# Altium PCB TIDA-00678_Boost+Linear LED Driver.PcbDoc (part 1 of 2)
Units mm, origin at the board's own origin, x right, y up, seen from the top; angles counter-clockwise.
Board outline 111.76 x 61.72 mm, 2 copper layers (Top Layer, Bottom Layer), stack 1.575 mm thick; 183 components, 81 nets, 485 pads, 326 vias.
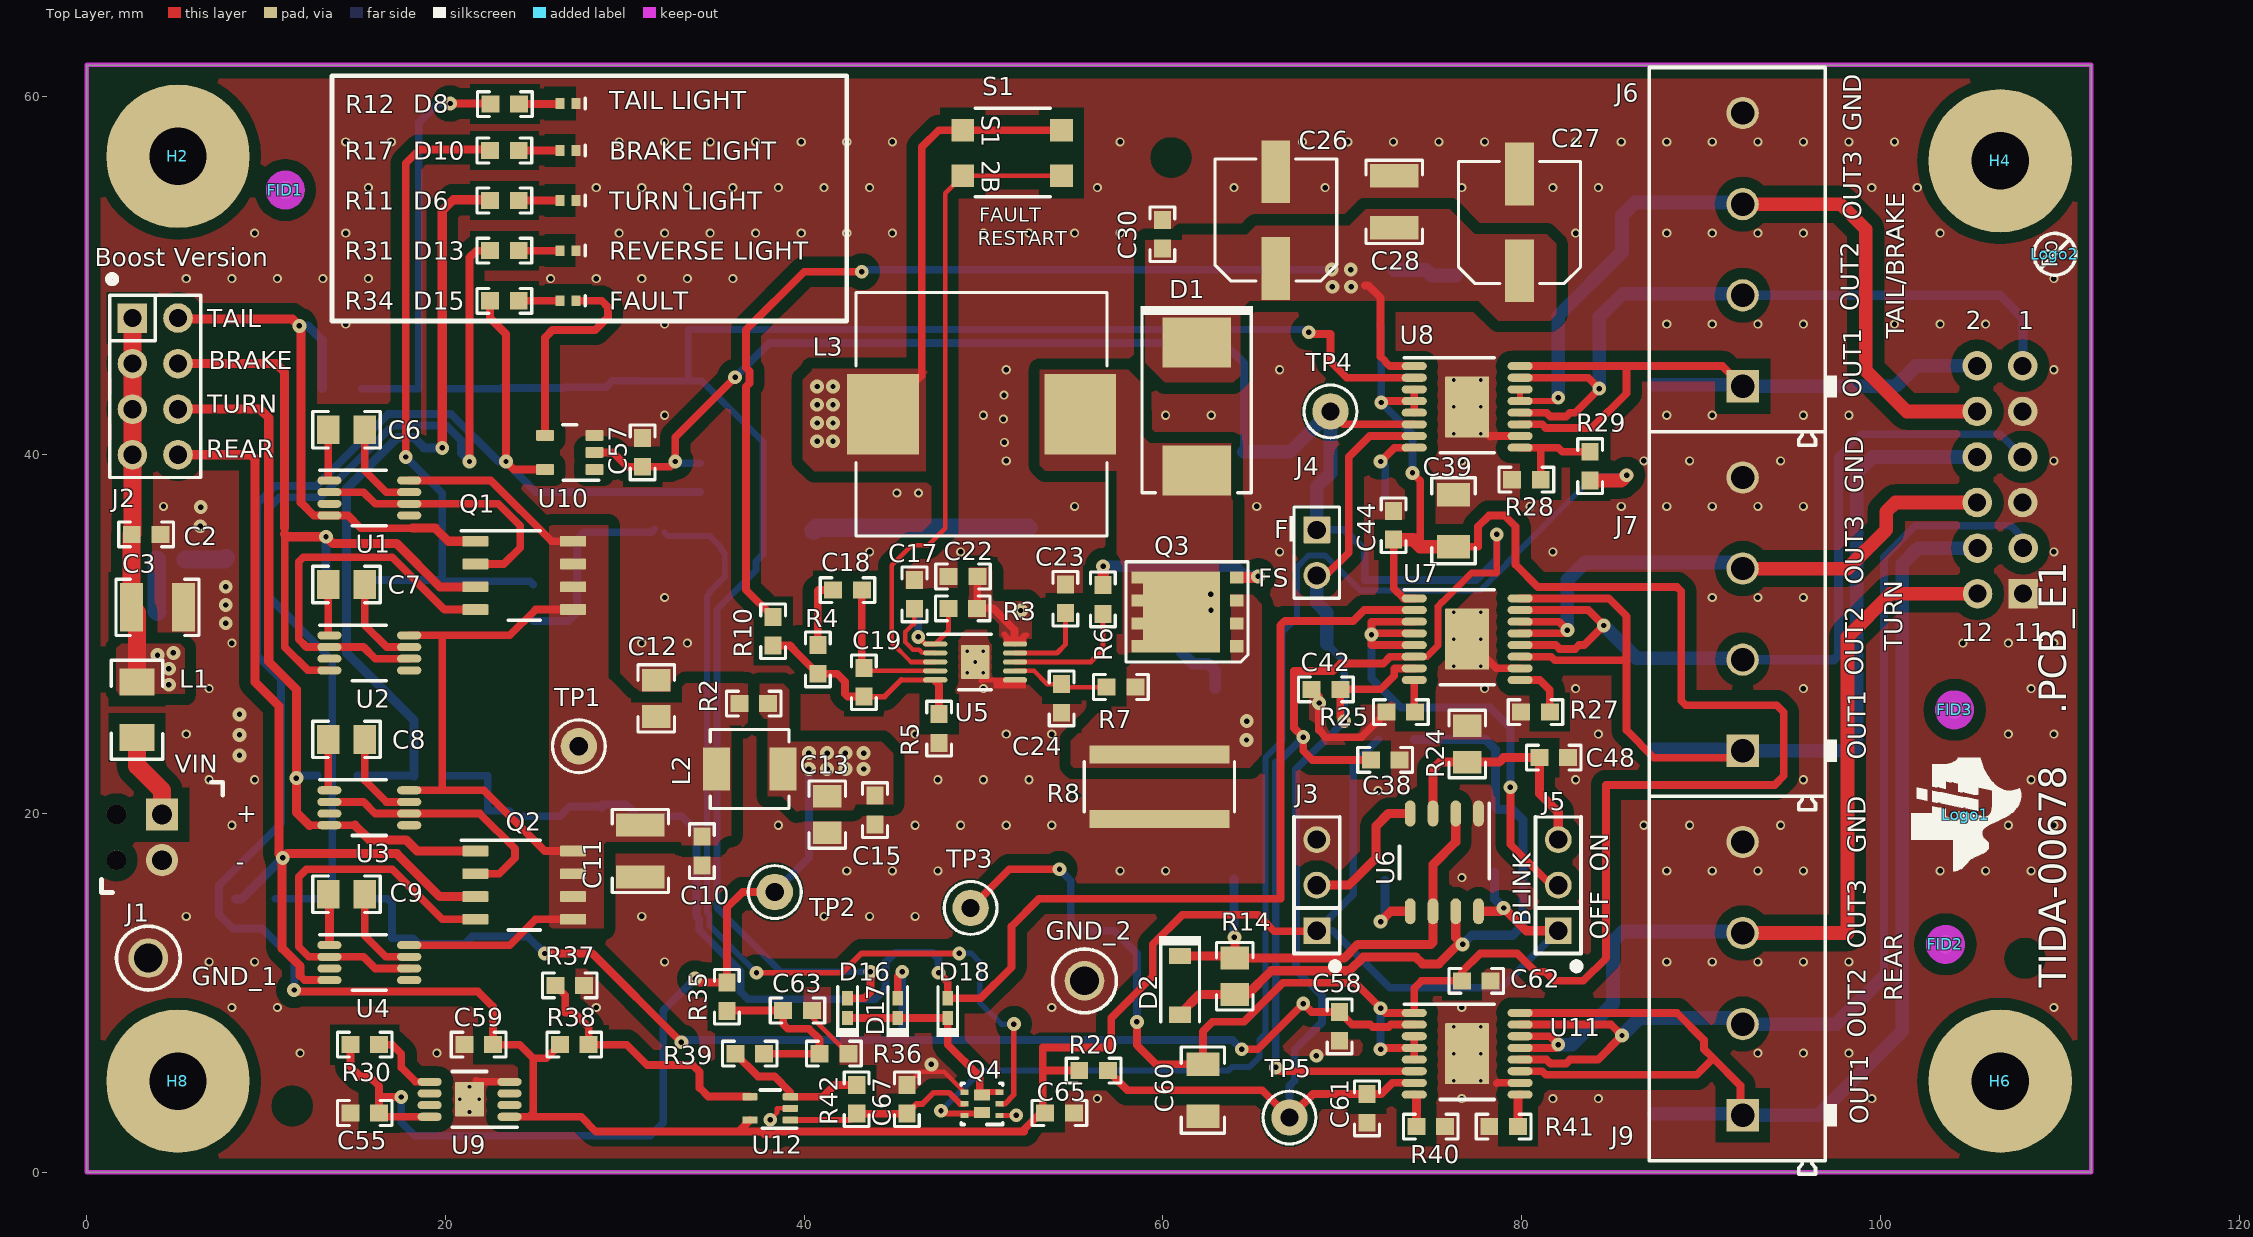
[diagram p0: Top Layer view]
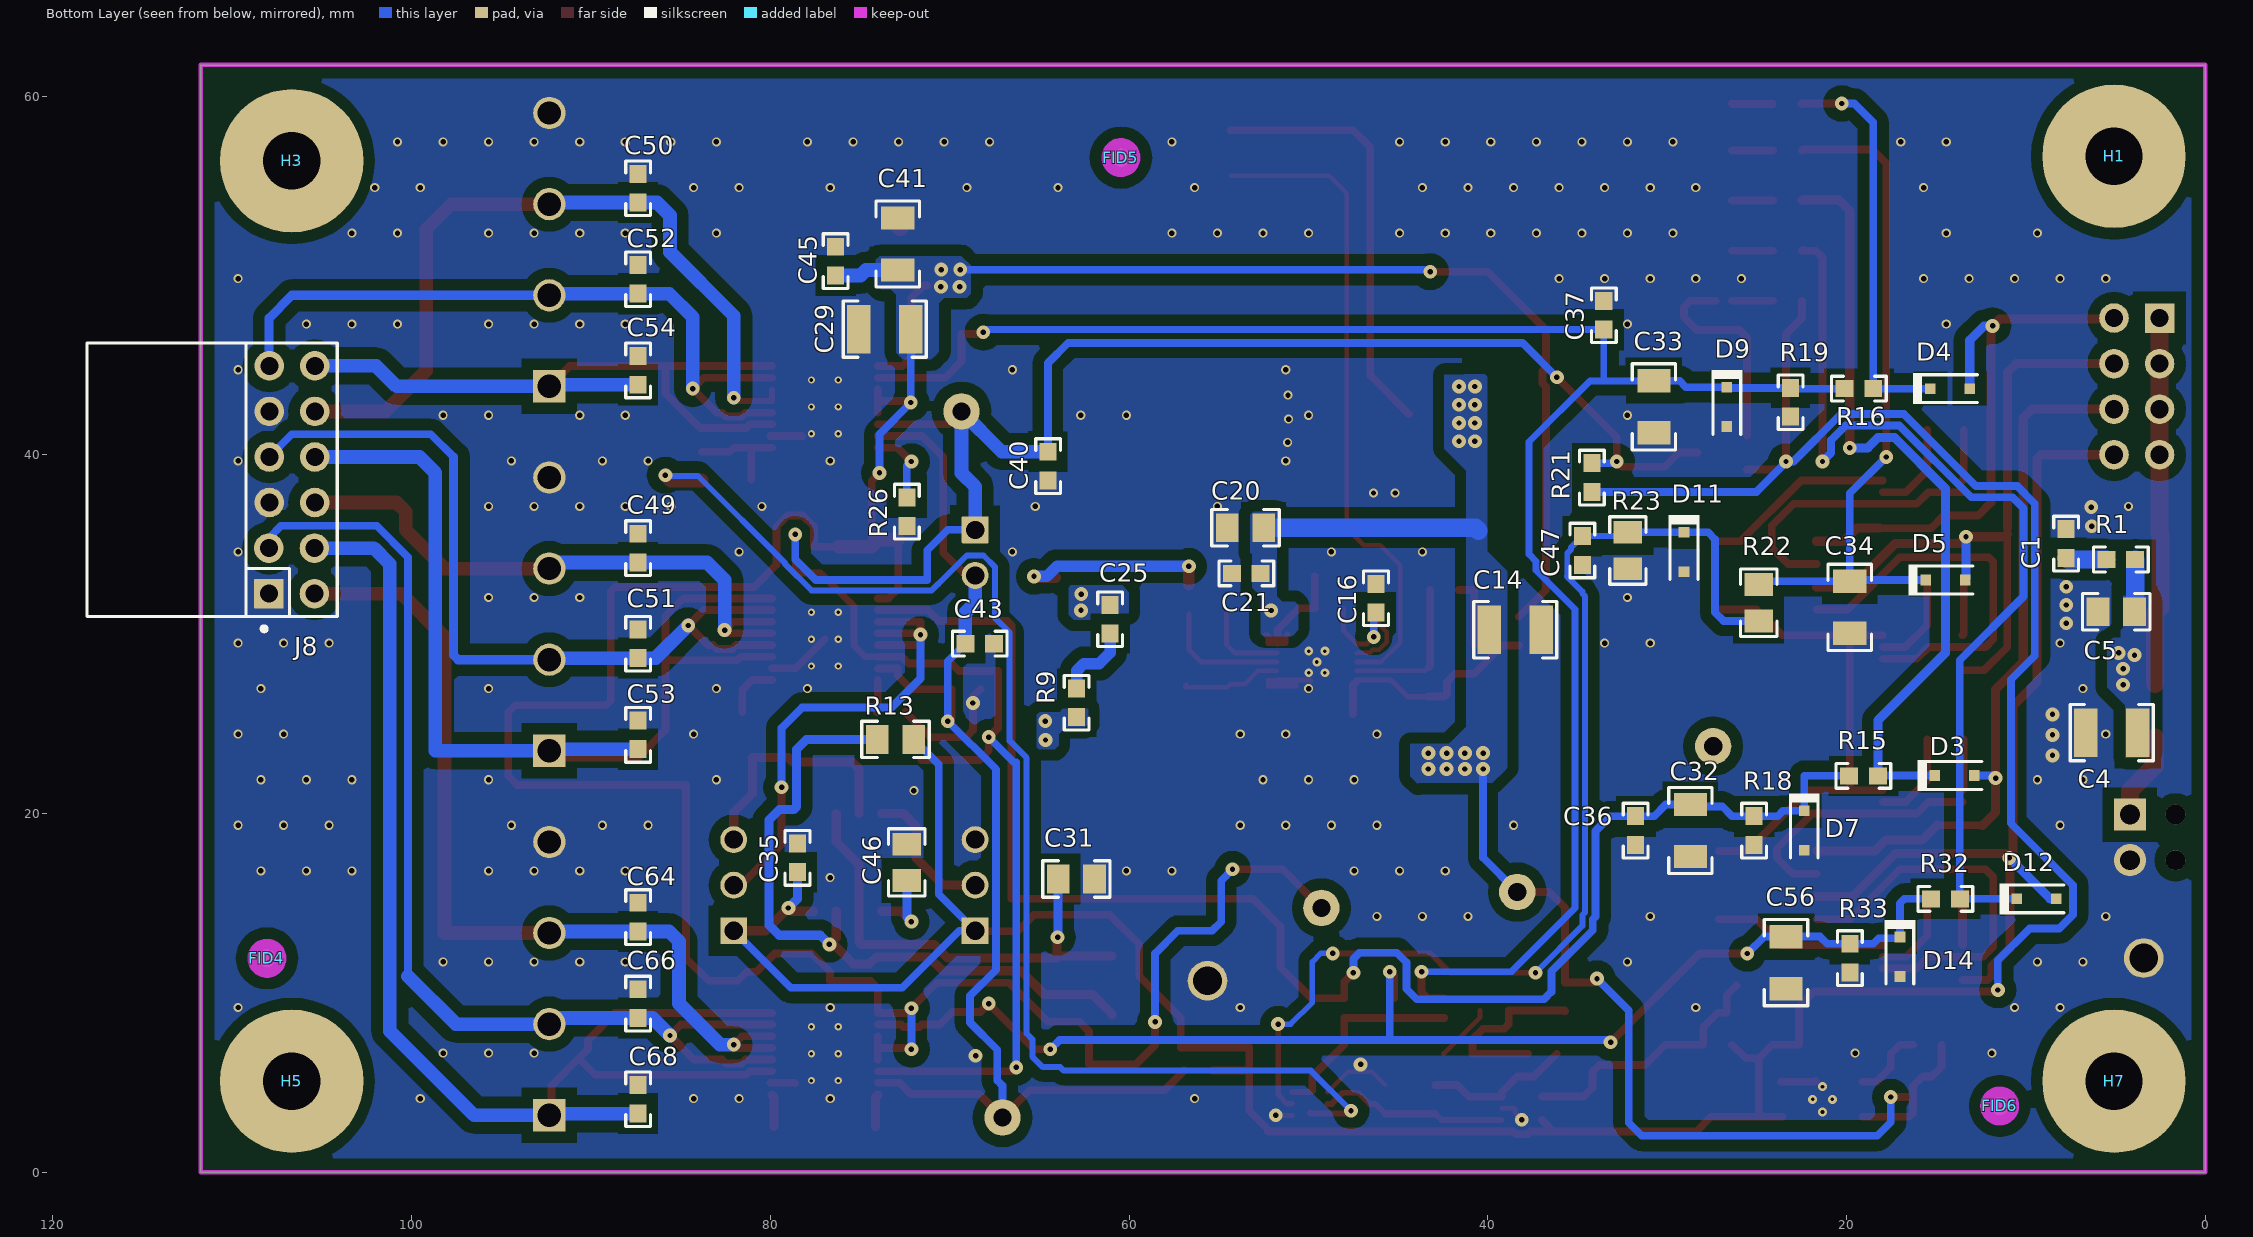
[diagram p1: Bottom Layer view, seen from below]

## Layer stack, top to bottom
Top Solder: solder mask 0.0102, Solder Resist, Dk 3.5
Top Layer: signal copper 0.0356
Dielectric1: core 1.5037, FR-4, Dk 4.8
Bottom Layer: signal copper 0.0356
Bottom Solder: solder mask 0.0102, Solder Resist, Dk 3.5

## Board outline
0,0 111.76,0 111.76,61.722 0,61.722

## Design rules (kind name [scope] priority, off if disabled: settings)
AcuteAngle [All] p1: minimum=4.50000000000000E+0001 checktracksonly=FALSE
AssemblyTestPointUsage [All] p1: valid=2
Clearance Clearance_Keepouts [((IsTrack Or IsArc) And Not InPoly) And IsFree and IsKeepOut vs ((IsTrack Or IsArc) And Not InPoly) And IsFree and IsKeepOut] p1: gap=0
Clearance Clearance_BoardEdge_MountingHoles [OnCopper and InComponentClass('Mounting Holes') vs IsKeepOut] p2: gap=0.762
Clearance Clearance_BoardEdge_Poly [OnCopper and InPoly vs IsKeepOut] p3: gap=0.635
Clearance Clearance_BoardEdge [OnCopper and Not InComponentClass('Logo') and not InComponentClass('FiducialMark') and not InRegion(1000,500,4000,800) and Not IsKeepout vs IsKeepOut] p4: gap=1.524
Clearance Clearance_Poly [InPolygon] p5: gap=0.635
Clearance [All] p6: gap=0.2
ComponentClearance ComponentClearance_MountingHoles_FiducialMarks [InComponentClass('Mounting Holes') vs InComponentClass('FiducialMark')] p1: gap=1.27 collisioncheckmode=3 verticalgap=0.254 showdistances=FALSE
ComponentClearance ComponentClearance_Shunt [InComponentClass('Header') vs InComponentClass('Shunt')] p2: gap=0 collisioncheckmode=3 verticalgap=0 showdistances=FALSE
ComponentClearance ComponentClearance_Logo [InComponentClass('Logo')] p3: gap=1.27 collisioncheckmode=3 verticalgap=0.254 showdistances=FALSE
ComponentClearance ComponentClearance_ScrewToNut [(HasFootprint('NY PMS 440 0025 PH')) vs (HasFootprint('Keystone_1902C'))] p4: gap=0.127 collisioncheckmode=3 verticalgap=0.254 showdistances=FALSE
ComponentClearance ComponentClearance_MountingHoles [InComponentClass('Mounting Holes')] p5: gap=0.762 collisioncheckmode=3 verticalgap=2540 showdistances=FALSE
ComponentClearance ComponentClearance_SmallPassives [HasFootprint('0201*') or HasFootprint('0402*') or HasFootprint('0508') or HasFootprint('0603*') or HasFootprint('0612') or HasFootprint('0805*') or HasFootprint('0815*') or HasFootprint('0830*') or HasFootprint('1206*') or HasFootprint('1210*') or HasFootprint('1808*') or HasFootprint('1812*') or HasFootprint('1825*') or HasFootprint('2010*') or HasFootprint('2220*') or HasFootprint('2225*') or HasFootprint('2512*') or HasFootprint('2728*') or HasFootprint('3518*') vs HasFootprint('0201*') or HasFootprint('0402*') or HasFootprint('0508') or HasFootprint('0603*') or HasFootprint('0612') or HasFootprint('0805*') or HasFootprint('0815*') or HasFootprint('0830*') or HasFootprint('1206*') or HasFootprint('1210*') or HasFootprint('1808*') or HasFootprint('1812*') or HasFootprint('1825*') or HasFootprint('2010*') or HasFootprint('2220*') or HasFootprint('2225*') or HasFootprint('2512*') or HasFootprint('2728*') or HasFootprint('3518*')] p6: gap=0.508 collisioncheckmode=3 verticalgap=0.254 showdistances=FALSE
ComponentClearance ComponentClearance_THtoSMT [IsThruComponent vs IsSMTComponent] p7: gap=2.54 collisioncheckmode=3 verticalgap=0.762 showdistances=FALSE
ComponentClearance ComponentClearance_THtoTH [IsThruComponent vs IsThruComponent] p8: gap=0 collisioncheckmode=3 verticalgap=0 showdistances=FALSE
ComponentClearance [All] p9: gap=1.016 collisioncheckmode=3 verticalgap=0.254 showdistances=FALSE
DiffPairsRouting [All] p1: maxlimit=2.54 minlimit=0.254 mostfreqgap=0.254 toplayer_minwidth=0.381 toplayer_maxwidth=0.381 toplayer_prefwidth=0.381 bottomlayer_minwidth=0.381 bottomlayer_maxwidth=0.381 bottomlayer_prefwidth=0.381 maxuncoupledlength=25.4
FabricationTestPointUsage TestPointUsage [All] p1: valid=2 allowmultiple=FALSE
FabricationTestpoint Testpoint [All] p1: side=3 testpointundercomponent=TRUE minsize=1.016 maxsize=2.54 preferedsize=1.524 minholesize=0 maxholesize=1.016 preferedholesize=0.813 testpointgrid=0.025 allowsidetop=TRUE allowsidebottom=TRUE usegrid=TRUE gridtolerance=0
FanoutControl Fanout_LCC [IsLCC] p1: bgadir=Out bgaviamode=Centered fanoutstyle=Auto fanoutdirection=Alternating viagrid=0.025 // Fanout_LCC (Default Rule)
FanoutControl Fanout_BGA [IsBGA] p2: bgadir=Out bgaviamode=Centered fanoutstyle=Auto fanoutdirection=Alternating viagrid=0.025 // Fanout_BGA (Default Rule)
FanoutControl Fanout_Default [All] p4: bgadir=Out bgaviamode=Centered fanoutstyle=Auto fanoutdirection=Alternating viagrid=0.025 // Fanout_Default (Default Rule)
FanoutControl Fanout_Small [(CompPinCount < 5)] p5: bgadir=Out bgaviamode=Centered fanoutstyle=Auto fanoutdirection=OutThenIn viagrid=0.025 // Fanout_Small (Default Rule)
HoleSize [All] p1: absolutevalues=TRUE maxlimit=6.375 minlimit=0.198 maxpercent=80.000 minpercent=20.000
MinimumAnnularRing MinimumAnnularRing_ThermalPadVias [IsVia and InAnyComponent] p1: minimumring=0.076
MinimumAnnularRing [All] p2: minimumring=0.102
MinimumSolderMaskSliver MinimumSolderMaskSliver_Logo [InComponentClass('Logo') vs InComponentClass('Logo')] p1: minsoldermaskwidth=0.018
MinimumSolderMaskSliver [All] p2: minsoldermaskwidth=0
PlaneConnect [All] p1: planeconnectstyle=Relief reliefexpansion=0.254 reliefentries=4 reliefconductorwidth=0.254 reliefairgap=0.254
PolygonConnect [All] p1: connectstyle=Direct reliefconductorwidth=0.254 reliefentries=4 polygonreliefangle="90 Angle" airgapwidth=0.254
RoutingVias ThermalPadVias [IsVia and InAnyComponent] p1: holewidth=0.2 width=0.5 viastyle="Through Hole" minholewidth=0.198 minwidth=0.351 maxholewidth=0.33 maxwidth=0.6
RoutingVias [All] p2: holewidth=0.406 width=0.864 viastyle="Through Hole" minholewidth=0.2 minwidth=0.508 maxholewidth=1.016 maxwidth=1.651
SilkToBoardRegionClearance [Not ((IsComment or IsDesignator) And (Hide <> 'False')) and not InRegion(1000,500,4000,800)] p1:
SilkToSilkClearance SilkToSilkClearance_Pb-FreeLogo [(HasFootprint('Pb-Free_Overlay_Medium') OR HasFootprint('Pb-Free_Overlay_Small')) vs (HasFootprint('Pb-Free_Overlay_Medium') OR HasFootprint('Pb-Free_Overlay_Small'))] p1: silktosilkclearance=0
SilkToSilkClearance [All] p2: silktosilkclearance=0
SilkToSolderMaskClearance SilkToComonentPadClearance [IsPad and InAnycomponent] p1: minsilkscreentomaskgap=0 clearancetoexposedcopper=TRUE
SilkToSolderMaskClearance "Silk to Solder Mask Opening" [All] p2: minsilkscreentomaskgap=0 clearancetoexposedcopper=FALSE
SolderMaskExpansion [All] p1: expansion=0.05
UnpouredPolygon [All] p1: allowunpoured=FALSE
Width [All] p1: maxlimit=2.54 minlimit=0.152 preferedwidth=0.254 checkconnectedcopper=TRUE
14 further rules are at their usual default settings.

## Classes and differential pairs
component class "TIDA-00678_Boost+Linear LED Driver 2": C31 C32 C33 C34 C35 C36 C37 C38 C39 C40 C41 C42 C43 C44 C45 C46 C47 C48 C49 C50 C51 C52 C53 C54 C55 C56 C57 C58 C59 C60 C61 C62 C63 C64 C65 C66 C67 C68 D2 D3 D4 D5 D6 D7 D8 D9 D10 D11 D12 D13 D14 D15 D16 D17 D18 GND_1 GND_2 J3 J4 J5 J6 J7 J8 J9 Q4 R11 R12 R13 R14 R15 R16 R17 R18 R19 R20 R21 R22 R23 R24 R25 R26 R27 R28 R29 R30 R31 R32 R33 R34 R35 R36 R37 R38 R39 R40 R41 R42 TP4 TP5 U6 U7 U8 U9 U10 U11 U12
component class "TIDA-00678_Boost+Linear LED Driver 1": C1 C2 C3 C4 C5 C6 C7 C8 C9 C10 C11 C12 C13 C14 C15 C16 C17 C18 C19 C20 C21 C22 C23 C24 C25 C26 C27 C28 C29 C30 D1 J1 J2 L1 L2 L3 L4 Q1 Q2 Q3 R1 R2 R3 R4 R5 R6 R7 R8 R9 R10 S1 TP1 TP2 TP3 U1 U2 U3 U4 U5
component class Header: J2 J3 J5
component class AssemblyNote: ZZ1 ZZ2 ZZ3 ZZ4
component class FiducialMark: FID1 FID2 FID3 FID4 FID5 FID6
component class "TIDA-00678_Boost+Linear LED Driver_TID_Hardware": FID1 FID2 FID3 FID4 FID5 FID6 H1 H2 H3 H4 H5 H6 H7 H8 Logo1 Logo2 ZZ1 ZZ2 ZZ3 ZZ4
component class Logo: Logo1
component class "Mounting Holes": H2 H4 H6 H8

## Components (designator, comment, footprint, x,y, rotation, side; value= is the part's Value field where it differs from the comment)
C1 "GRM188R72A102KA01D" 0603 7.747,35.052 r90 bottom
C2 "GRM188R71H473KA61D" 0603 3.302,35.56 r0 top
C3 "GRM32ER71H106KA12L" 1210_270 3.937,31.496 r0 top
C4 "GRM32ER71H106KA12L" 1210_270 5.207,24.511 r0 bottom
C5 "C2012JB1V226M125AC" 0805_HV 4.953,31.242 r0 bottom
C6 "C2012X5R1H225K125AB" 0805_HV 14.478,41.402 r180 top
C7 "C2012X5R1H225K125AB" 0805_HV 14.478,32.766 r180 top
C8 "C2012X5R1H225K125AB" 0805_HV 14.478,24.13 r180 top
C9 "C2012X5R1H225K125AB" 0805_HV 14.478,15.494 r180 top
C10 "GRM188R72A102KA01D" 0603 34.29,17.907 r270 top
C11 "GRM32ER71H106KA12L" 1210_270 30.861,17.907 r270 top
C12 "C2012JB1V226M125AC" 0805_HV 31.75,26.416 r90 top
C13 "C2012JB1V226M125AC" 0805_HV 41.275,19.939 r270 top
C14 "GRM32ER71H106KA12L" 1210_270 38.464,30.246 r180 bottom
C15 "C1608X7R1H104K080AA" 0603 43.942,20.193 r270 top
C16 "06035A221FAT2A" 0603 46.228,32.004 r90 bottom
C17 "C0603C224K4RACTU" 0603 46.145,32.215 r90 top
C18 "06035A561JAT2A" 0603 42.412,32.457 r180 top
C19 "06035A8R2CAT2A" 0603 43.324,27.321 r270 top
C20 "C2012JB1V226M125AC" 0805_HV 53.508,35.938 r180 bottom
C21 "UMK107AB7105KA-T" 0603 53.459,33.386 r180 bottom
C22 "C1608X7R1H104K080AA" 0603 48.852,33.212 r0 top
C23 "GRM185C81A105KE36D" 0603 54.559,31.97 r90 top
C24 "06035A101FAT2A" 0603 54.356,26.416 r270 top
C25 "06035A561JAT2A" 0603 61.055,30.831 r270 bottom
C26 "UUD1V680MCL1GS" SM_RADIAL_6.3BMM 66.294,53.086 r90 top
C27 "EEHZA1H330XP" SM_RADIAL_6.3BMM 79.883,52.959 r90 top
C28 "GRM32ER71H106KA12L" 1210_270 72.898,54.102 r90 top
C29 "GRM32ER71H106KA12L" 1210_270 73.621,47.012 r0 bottom
C30 "C1608X7R1H104K080AA" 0603 59.971,52.297 r90 top
C31 "GRM219R71E824KA88D" 0805_HV 62.936,16.347 r180 bottom
C32 "GRM31CR71H475KA12L" 1206 28.702,19.05 r90 bottom
C33 "GRM31CR71H475KA12L" 1206 30.734,42.672 r90 bottom
C34 "GRM31CR71H475KA12L" 1206 19.812,31.496 r270 bottom
C35 "06035C104KAT2A" 0603 78.486,17.526 r270 bottom
C36 "06035C104KAT2A" 0603 31.75,19.05 r90 bottom
C37 "06035C104KAT2A" 0603 33.531,47.777 r270 bottom
C38 "06035C104KAT2A" 0603 72.39,22.987 r0 top
C39 "GRM31CR71H475KA12L" 1206 76.2,36.322 r270 top
C40 "06035C104KAT2A" 0603 64.516,39.37 r270 bottom
C41 "GRM31CR71H475KA12L" 1206 72.898,51.752 r270 bottom
C42 "06035C104KAT2A" 0603 69.088,26.924 r180 top
C43 "06035C104KAT2A" 0603 68.326,29.464 r180 bottom
C44 "06035C104KAT2A" 0603 72.865,36.068 r270 top
C45 "06035C104KAT2A" 0603 76.358,50.8 r270 bottom
C46 "0805YC224JAT2A" 0805_HV 72.39,17.272 r90 bottom
C47 "06035C104KAT2A" 0603 34.726,34.663 r270 bottom
C48 "06031C103JAT2A" 0603 81.788,23.114 r0 top
C49 "06031C103JAT2A" 0603 87.378,34.798 r270 bottom
C50 "06031C103JAT2A" 0603 87.378,54.864 r270 bottom
C51 "06031C103JAT2A" 0603 87.378,29.464 r270 bottom
C52 "06031C103JAT2A" 0603 87.378,49.784 r270 bottom
C53 "06031C103JAT2A" 0603 87.378,24.384 r270 bottom
C54 "06031C103JAT2A" 0603 87.376,44.704 r270 bottom
C55 "C1608X7R1H104K" 0603 15.494,3.302 r180 top
C56 "GRM31CR71H475KA12L" 1206 23.368,11.684 r90 bottom
C57 "0603YC104JAT2A" 0603 30.988,40.132 r90 top
C58 "06035C104KAT2A" 0603 69.85,8.128 r90 top
C59 "C1608X5R1A226M080AC" 0603 21.844,7.112 r180 top
C60 "GRM31CR71H475KA12L" 1206 62.23,4.572 r90 top
C61 "06035C104KAT2A" 0603 71.374,3.556 r270 top
C62 "06035C104KAT2A" 0603 77.47,10.668 r180 top
C63 "06035C104KAT2A" 0603 39.624,9.017 r0 top
C64 "06031C103JAT2A" 0603 87.378,14.224 r270 bottom
C65 "0603YC104JAT2A" 0603 54.229,3.302 r180 top
C66 "06031C103JAT2A" 0603 87.378,9.398 r270 bottom
C67 "0603YC104JAT2A" 0603 45.72,4.064 r270 top
C68 "06031C103JAT2A" 0603 87.378,4.064 r270 bottom
D1 "MBRS340T3G" SMC 61.879,42.685 r270 top
D2 "1N4148W-7-F" SOD-123 60.96,10.414 r270 top
D3 "PMEG6010CEJ,115" SOD-323F 13.97,22.12 r180 bottom
D4 "PMEG6010CEJ,115" SOD-323F 14.224,43.688 r180 bottom
D5 "PMEG6010CEJ,115" SOD-323F 14.478,33.02 r180 bottom
D6 "SML-P12PTT86" SML-P1_GREEN 26.835,54.177 r180 top
D7 "BZT52C9V1S-7-F" sod-323 22.352,19.05 r270 bottom
D8 "SML-P12PTT86" SML-P1_GREEN 26.834,59.586 r180 top
D9 "BZT52C9V1S-7-F" sod-323 26.67,42.672 r270 bottom
D10 "SML-P12PTT86" SML-P1_GREEN 26.835,56.971 r180 top
D11 "MMSZ5229BS-7-F" sod-323 29.055,34.575 r270 bottom
D12 "PMEG6010CEJ,115" SOD-323F 9.398,15.24 r180 bottom
D13 "SML-P12PTT86" SML-P1_GREEN 26.835,51.383 r180 top
D14 "BZT52C9V1S-7-F" sod-323 17.018,12.009 r270 bottom
D15 "SML-P12UTT86" SML-P1_RED 26.835,48.589 r180 top
D16 "SBR0220T5-7-F" SOD-523 42.418,9.144 r90 top
D17 "SBR0220T5-7-F" SOD-523 45.212,9.144 r90 top
D18 "SBR0220T5-7-F" SOD-523 48.006,9.144 r90 top
FID1 "Fiducial" Fiducial10-20 11.062,54.763 r0 top
FID2 "Fiducial" Fiducial10-20 103.632,12.7 r0 top
FID3 "Fiducial" Fiducial10-20 104.14,25.781 r0 top
FID4 "Fiducial" Fiducial10-20 108.067,11.924 r180 bottom
FID5 "Fiducial" Fiducial10-20 60.451,56.572 r180 bottom
FID6 "Fiducial" Fiducial10-20 11.451,3.691 r180 bottom
GND_1 "5011" Keystone5011 3.429,11.938 r0 top
GND_2 "5011" Keystone5011 55.626,10.668 r0 top
H1 "1902C" Keystone_1902C 5.08,56.642 r180 bottom locked
H2 "NY PMS 440 0025 PH" "NY PMS 440 0025 PH" 5.08,56.642 r0 top locked
H3 "1902C" Keystone_1902C 106.68,56.388 r180 bottom locked
H4 "NY PMS 440 0025 PH" "NY PMS 440 0025 PH" 106.68,56.388 r0 top locked
H5 "1902C" Keystone_1902C 106.68,5.08 r180 bottom locked
H6 "NY PMS 440 0025 PH" "NY PMS 440 0025 PH" 106.68,5.08 r0 top locked
H7 "1902C" Keystone_1902C 5.08,5.08 r180 bottom locked
H8 "NY PMS 440 0025 PH" "NY PMS 440 0025 PH" 5.08,5.08 r0 top locked
J1 "1725656" CONN_1725656 4.191,18.669 r270 top
J2 "PEC04DAAN" CONN_PEC04DAAN 3.81,43.815 r270 top
J3 "PEC03SAAN" CONN_PEC03SAAN 68.58,16.002 r90 top
J4 "PEC02SAAN" CONN_PEC02SAAN 68.58,34.544 r270 top
J5 "PEC03SAAN" CONN_PEC03SAAN 82.042,16.002 r90 top
J6 "1715747" Phoenix_1715747 92.324,51.435 r90 top
J7 "1715747" Phoenix_1715747 92.324,31.115 r90 top
J8 "SSQ-106-02-G-D-RA" SSQ-106-02-G-D-RA 106.68,38.608 r270 bottom
J9 "1715747" Phoenix_1715747 92.324,10.795 r90 top
L1 "HI1206T161R-10" 1206M 2.794,25.781 r90 top
L2 "744373240047" WE-LHMI_4020 36.957,22.479 r0 top
L3 "SRP1250-100M" SRP1250 49.892,42.26 r180 top
Logo1 "Texas Instruments" TI_Symbol_Overlay_Medium 104.775,19.939 r90 top
Logo2 "Pb-Free Symbol" Pb-Free_Overlay_Small 109.728,51.181 r90 top
Q1 "SQ9945BEY-T1-GE3" SOIC-8 24.384,33.274 r0 top
Q2 "SQ9945BEY-T1-GE3" SOIC-8 24.384,16.002 r0 top
Q3 "CSD18531Q5A" TRANS_NexFET_Q5A 61.341,31.242 r180 top
Q4 "CSD85301Q2" DQK0006B 49.911,3.81 r180 top
R1 "CRCW06032R00FKEA" 0603 4.699,34.163 r180 bottom
R2 "CRCW06030000Z0EA" 0603 37.181,26.125 r180 top
R3 "CRCW0603160KFKEA" 0603 48.836,31.44 r0 top
R4 "CRCW0603102KFKEA" 0603 40.754,28.593 r90 top
R5 "CRCW06032K20JNEA" 0603 47.519,24.736 r90 top
R6 "CRCW060343R0JNEA" 0603 56.646,31.935 r90 top
R7 "CRCW06031K00FKEA" 0603 57.658,27.051 r0 top
R8 "KRL7638-C-R010-F-T1" 3015 59.8,21.49 r90 top
R9 "CRCW060310R0JNEA" 0603 62.922,26.172 r90 bottom
R10 "RC0603FR-0751K1L" 0603 38.263,30.165 r90 top
R11 "CRCW06033K30JNEA" 0603 23.279,54.177 r180 top
R12 "CRCW06033K30JNEA" 0603 23.306,59.556 r180 top
R13 "CRCW0805680KJNEA" 0805_HV 73.025,24.13 r180 bottom
R14 "CRCW0805680KJNEA" 0805_HV 64.008,10.922 r270 top
R15 "RC0603FR-0759KL" 0603 19.05,22.098 r0 bottom
R16 "RC0603FR-0759KL" 0603 19.304,43.688 r0 bottom
R17 "CRCW06033K30JNEA" 0603 23.279,56.971 r180 top
R18 "RC0603FR-0742K2L" 0603 25.146,19.05 r90 bottom
R19 "RC0603FR-0742K2L" 0603 23.114,42.926 r90 bottom
R20 "CRCW0603100KFKEA" 0603 56.134,5.664 r180 top
R21 "CRCW0603100KFKEA" 0603 34.197,38.731 r270 bottom
R22 "CRCW080521K5FKEA" 0805_HV 24.892,31.75 r90 bottom
R23 "CRCW080520K0JNEA" 0805_HV 32.186,34.663 r90 bottom
R24 "CRCW0805100KFKEA" 0805_HV 76.962,23.876 r270 top
R25 "CRCW06030000Z0EA" 0603 73.264,25.654 r0 top
R26 "CRCW06030000Z0EA" 0603 72.39,36.83 r90 bottom
R27 "CRCW06031K21FKEA" 0603 80.772,25.654 r0 top
R28 "CRCW06031K21FKEA" 0603 80.264,38.608 r0 top
R29 "CRCW06032K43FKEA" 0603 83.82,39.37 r90 top
R30 "CRCW060310K0FKEA" 0603 15.494,7.112 r180 top
R31 "CRCW06033K30JNEA" 0603 23.279,51.383 r180 top
R32 "RC0603FR-0759KL" 0603 14.478,15.24 r0 bottom
R33 "RC0603FR-0742K2L" 0603 19.812,11.938 r90 bottom
R34 "RC0603FR-07470RL" 0603 23.279,48.589 r180 top
R35 "RC0603FR-0757K6L" 0603 35.687,9.779 r90 top
R36 "CRCW060310K0FKEA" 0603 41.656,6.604 r180 top
R37 "CRCW060310K0FKEA" 0603 27.178,7.112 r180 top
R38 "CRCW060310K0FKEA" 0603 26.924,10.414 r180 top
R39 "RC0603FR-072K55L" 0603 36.957,6.604 r180 top
R40 "CRCW06030000Z0EA" 0603 74.93,2.54 r180 top
R41 "CRCW06031K21FKEA" 0603 78.994,2.54 r0 top
R42 "RC0603FR-0747KL" 0603 42.926,4.064 r90 top
S1 "7914G-1-000E" SW_7914G-1-000E 51.588,56.83 r270 top
TP1 "5000" Keystone5000 27.432,23.749 r0 top
TP2 "5000" Keystone5000 38.354,15.621 r0 top
TP3 "5000" Keystone5000 49.276,14.732 r0 top
TP4 "5000" Keystone5000 69.342,42.418 r0 top
TP5 "5000" Keystone5000 67.056,3.048 r0 top
U1 "LM74610QDGKRQ1" DGK0008A_N 15.748,37.592 r0 top
U2 "LM74610QDGKRQ1" DGK0008A_N 15.748,28.956 r0 top
U3 "LM74610QDGKRQ1" DGK0008A_N 15.748,20.32 r0 top
U4 "LM74610QDGKRQ1" DGK0008A_N 15.748,11.684 r0 top
U5 "TPS40210QDGQRQ1" DGQ0010D_N 49.53,28.448 r0 top
U6 "TLC555CD" D0008A_N 75.692,17.272 r270 top
U7 "TPS92630QPWPRQ1" PWP0016F_N 76.962,29.718 r0 top
U8 "TPS92630QPWPRQ1" PWP0016F_N 76.962,42.672 r0 top
U9 "TPS7A1633QDGNRQ1" DGN0008C_N 21.336,4.064 r180 top
U10 "SN74LVC1G07DBVR" DBV0005A_N 26.924,40.132 r180 top
U11 "TPS92630QPWPRQ1" PWP0016F_N 76.962,6.604 r0 top
U12 "LMV7239QM7" DCK0005A_N 38.1,3.556 r180 top
ZZ1 "This Assembly Note will show in the PcbDoc and associated outputs" AssemblyNote 4.699,97.259 r0 top
ZZ2 "This Assembly Note will show in the PcbDoc and associated outputs" AssemblyNote 4.699,95.01 r0 top
ZZ3 "This Assembly Note will show in the PcbDoc and associated outputs" AssemblyNote 4.699,92.761 r0 top

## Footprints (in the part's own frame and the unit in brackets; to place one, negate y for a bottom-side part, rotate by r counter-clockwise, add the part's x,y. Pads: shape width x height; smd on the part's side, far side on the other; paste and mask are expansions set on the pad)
0603 [mm] "0603 from SM-752 data"
  rect 1x0.95 smd: 1(-0.8,0) 2(0.8,0)
  silkscreen extent -1.52,-0.69 1.52,0.69, body extent -0.87,-0.47 0.87,0.47, height 1
0805_HV [mil] "0805 with 30mil clearance between pads"
  rect 50x63 smd: 1(-40,0) 2(40,0)
  silkscreen extent -74,-40 74,40, body extent -43,-29 43,29, height 57
1206 [mm] "1206 from SM-752 data"
  rect 1.3x1.85 smd: 1(-1.45,0) 2(1.45,0)
  silkscreen extent -2.4,-1.21 2.4,1.21, body extent -1.7,-0.9 1.7,0.9, height 1.35
1206M [mm] "1206 from SM-752 data"
  rect 1.5x1.95 smd: 1(-1.55,0) 2(1.55,0)
  silkscreen extent -2.76,-1.44 2.76,1.44, body extent -1.7,-0.9 1.7,0.9, height 1.35
1210_270 [mm] "1210"
  rect 1.3x2.7 smd: 1(-1.45,0) 2(1.45,0)
  silkscreen extent -2.32,-1.57 2.32,1.57, body extent -1.7,-1.35 1.7,1.35, height 2.7
3015 [mm] "Susumu recommended land pattern"
  rect 1x7.8 smd: 1(-1.8,0) 2(1.8,0)
  silkscreen extent -1.4,-4.19 1.4,4.19, body extent -2,-3.9 2,3.9, height 0.7
AssemblyNote [mm] "Assembly Note"
CONN_1725656 [mm] "Phoenix Contact"
  rect 1.8x1.8 hole 1.1: 1(-1.27,0)
  round 1.8 hole 1.1: 2(1.27,0)
  round 1.1 hole 1.1 unplated: MH1(-1.275,-2.54) MH2(1.27,-2.54)
  silkscreen extent -3.08,-3.37 3.08,3.37, body extent -2.77,-3.1 2.77,3.1, height 8.52
CONN_PEC02SAAN [mm] "SULLINS"
  rrect7% 1.5x1.5 hole 1.016: 1(-1.27,0)
  round 1.5 hole 1.016: 2(1.27,0)
  silkscreen extent -2.54,-1.52 2.54,1.27, body extent -2.54,-1.27 2.54,1.27, height 8.38
CONN_PEC03SAAN [mm] "SULLINS"
  rect 1.5x1.5 hole 1.016: 1(-2.54,0)
  round 1.5 hole 1.016: 2(0,0) 3(2.54,0)
  silkscreen extent -4.72,-1.27 3.81,1.27, body extent -3.84,-1.3 3.84,1.3, height 8.38
CONN_PEC04DAAN [mm] "SULLINS"
  rect 1.65x1.65 hole 1.016 mask+0: 1(-3.81,-1.27)
  round 1.65 hole 1.016 mask+0: 2(-3.81,1.27) 3(-1.27,-1.27) 4(-1.27,1.27) 5(1.27,-1.27) 6(1.27,1.27) 7(3.81,-1.27) 8(3.81,1.27)
  silkscreen extent -6.18,-2.6 5.08,2.54, body extent -5.08,-2.54 5.08,2.54, height 8.38
D0008A_N [mm] "SOIC, 8-Leads, Body 4.9x3.9mm, Pitch 1.27mm, IPC Medium Density"
  oval 1.45x0.6 smd: 1(-2.725,1.905) 2(-2.725,0.635) 3(-2.725,-0.635) 4(-2.725,-1.905) 5(2.725,-1.905) 6(2.725,-0.635) 7(2.725,0.635) 8(2.725,1.905)
  silkscreen extent -3.3,-2.5 0.9,2.5, body extent -3,-2.45 3,2.45, height 1.63
DBV0005A_N [mm] "SOT23, 5-Leads, Body 2.9x1.6mm, Pitch 0.95mm, Lead Span 2.8mm, IPC Medium Density"
  rrect17% 1x0.6 smd: 1(-1.375,0.95) 2(-1.375,0) 3(-1.375,-0.95) 4(1.375,-0.95) 5(1.375,0.95)
  silkscreen extent -1.63,-1.55 0.38,1.55, body extent -1.42,-1.46 1.42,1.46, height 1.09
DCK0005A_N [mm] "SOT353, 5-Leads, Body 2x1.3mm, Pitch 0.65mm, Lead Span 2.1mm, IPC Medium Density"
  rrect25% 0.85x0.4 smd: 1(-1.125,0.65) 2(-1.125,0) 3(-1.125,-0.65) 4(1.125,-0.65) 5(1.125,0.65)
  silkscreen extent -1.48,-1.02 0.55,1.1, body extent -1.14,-1 1.14,1, height 0.95
DGK0008A_N [mm] "TSOP, 8-Leads, Body 3x3mm, Pitch 0.65mm, IPC Medium Density"
  oval 1.35x0.45 smd: 1(-2.225,0.975) 2(-2.225,0.325) 3(-2.225,-0.325) 4(-2.225,-0.975) 5(2.225,-0.975) 6(2.225,-0.325) 7(2.225,0.325) 8(2.225,0.975)
  silkscreen extent -2.75,-1.55 0.95,1.55, body extent -2.45,-1.5 2.45,1.5, height 0.96
DGN0008C_N [mm] "TSOP, 8-Leads, Body 3x3mm, Pitch 0.65mm, Thermal Pad 1.98x1.88mm, IPC Medium Density"
  rrect100% 1.35x0.45 smd: 1(-2.225,0.975) 2(-2.225,0.325) 3(-2.225,-0.325) 4(-2.225,-0.975) 5(2.225,-0.975) 6(2.225,-0.325) 7(2.225,0.325) 8(2.225,0.975)
  rrect6% 1.6x1.92 smd: 9(0,0)
  silkscreen extent -2.65,-1.55 0.95,1.55, body extent -2.46,-1.5 2.46,1.5, height 1.1
DGQ0010D_N [mm] "TSSOP, 10-Leads, Body 3x3mm, Pitch 0.5mm, Thermal Pad 1.88x1.57mm, IPC Medium Density"
  rrect100% 1.35x0.3 smd: 1(-2.225,1) 2(-2.225,0.5) 3(-2.225,0) 4(-2.225,-0.5) 5(-2.225,-1) 6(2.225,-1) 7(2.225,-0.5) 8(2.225,0) 9(2.225,0.5) 10(2.225,1)
  rrect6% 1.57x1.88 smd: 11(0,0)
  silkscreen extent -2.65,-1.55 0.9,1.55, body extent -2.46,-1.5 2.46,1.5, height 1.1
DQK0006B [mm] "TI"
  rect 0.45x0.3 smd: 1(-0.975,0.65) 2(-0.975,0) 3(-0.975,-0.65) 4(0.975,-0.65) 5(0.975,0) 6(0.975,0.65)
  rect 0.9x0.625 smd paste-0.025: 7(0,0.488) 8(0,-0.488)
  silkscreen extent -1.15,-1.15 1.15,1.15, body extent -1.05,-1.05 1.05,1.05, height 0.8
Fiducial10-20 [mm]
  round 1 smd mask+0.5: 1(0,0)
  Top Layer keep-out circle w1.178: c0,0 r0.5
Keystone5000 [mil] "For Keystone 500x miniature loop terminals"
  round 80 hole 40: 1(0,0)
  silkscreen extent -58,-58 58,58, body extent -49,-49 49,49, height 182
Keystone5011 [mil] "Keystone Multipurpose loops"
  round 87 hole 63: 1(0,0)
  silkscreen extent -70,-70 70,70, body extent -63,-63 63,62, height 319
Keystone_1902C [mil] "Hex Standoff, 4-40 threaded, nylon"
  round 1 on Mech4: 0(0,0)
  body extent -145,-126 146,126, height 501
"NY PMS 440 0025 PH" [mm] "4-40 nylon screw and mounting hole"
  round 8 hole 3.2: 1(0,0)
  body extent -3.3,-3.3 3.3,3.3, height 2.69
Pb-Free_Overlay_Small [mm]
  silkscreen extent -1.17,-1.17 1.17,1.16
Phoenix_1715747 [mm] "Terminal Block, 5.08mm, 4x1, TH"
  rect 1.8x1.8 hole 1.3: 1(-7.62,0)
  round 1.8 hole 1.3: 2(-2.54,0) 3(2.54,0) 4(7.62,0)
  silkscreen extent -10.9,-5.25 10.16,5.2, body extent -10.9,-4.6 10.16,5.2, height 14.2
PWP0016F_N [mm] "TSOP, 16-Leads, Body 5x4.4mm, Pitch 0.65mm, Thermal Pad 2.46x3.4 mm, IPC Medium Density"
  rrect100% 1.4x0.45 smd: 1(-2.95,2.275) 2(-2.95,1.625) 3(-2.95,0.975) 4(-2.95,0.325) 5(-2.95,-0.325) 6(-2.95,-0.975) 7(-2.95,-1.625) 8(-2.95,-2.275) 9(2.95,-2.275) 10(2.95,-1.625) 11(2.95,-0.975) 12(2.95,-0.325) 13(2.95,0.325) 14(2.95,0.975) 15(2.95,1.625) 16(2.95,2.275)
  rrect4% 2.46x3.4 smd: 17(0,0)
  silkscreen extent -3.5,-2.55 1.5,2.75, body extent -3.21,-2.5 3.21,2.5, height 1
SM_RADIAL_6.3BMM [mm] "Nichicon 6.3x7.7"
  rect 3.5x1.6 smd: 1(-2.7,0) 2(2.7,0)
  silkscreen extent -3.4,-3.4 3.4,3.4, body extent -3.41,-3.41 3.41,3.41, height 8
SMC [mil] "Molded Diode, 2-Leads, Body 6.9x5.8mm, IPC Medium Density, based on OnSemi component dimensions and land patterns"
  rect 110x150 smd: 1(-140.49,0) 2(140.49,0)
  silkscreen extent -221,-124 189,123, body extent -156,-116 156,116, height 91
SML-P1_GREEN [mm] "ROHM"
  rect 0.5x0.6 smd: 1(-0.45,0) 2(0.45,0)
  silkscreen extent -0.95,-0.3 -0.95,0.3, body extent -0.53,-0.33 0.53,0.33, height 0.25
SML-P1_RED [mm] "ROHM"
  rect 0.5x0.6 smd: 1(-0.45,0) 2(0.45,0)
  silkscreen extent -0.95,-0.3 -0.95,0.3, body extent -0.52,-0.33 0.52,0.33, height 0.25
SOD-123 [mm] "On Semi recommended land pattern"
  rect 0.915x1.22 smd: 1(-1.637,0) 2(1.637,0)
  silkscreen extent -2.74,-1.17 2.03,1.17, body extent -1.93,-0.9 1.93,0.9, height 1.35
sod-323 [mm] "NXP recommended land pattern"
  rect 0.6x0.6 smd paste-0.05: 1(-1.1,0) 2(1.1,0)
  silkscreen extent -2.06,-0.86 1.53,0.86, body extent -1.3,-0.67 1.3,0.68, height 1.1
SOD-323F [mm] "NXP recommended land pattern"
  rect 0.6x0.6 smd paste-0.05: 1(-1.1,0) 2(1.1,0)
  silkscreen extent -2.06,-0.86 1.53,0.86, body extent -1.35,-0.67 1.35,0.67, height 0.79
SOD-523 [mm] "NXP Semiconductor recommended land pattern, nominal STEP model"
  rect 0.8x0.6 smd paste-0.05: 1(-0.55,0) 2(0.55,0)
  silkscreen extent -1.6,-0.64 1.2,0.63, body extent -0.8,-0.4 0.8,0.4, height 0.72
SOIC-8 [mm] "duplicate of SO-8.  SOIC, 8-Leads, Body 5.0x4.0mm (max), Pitch 1.27mm, IPC Medium Density"
  rrect17% 1.45x0.6 smd: 1(-2.725,1.905) 2(-2.725,0.635) 3(-2.725,-0.635) 4(-2.725,-1.905) 5(2.725,-1.905) 6(2.725,-0.635) 7(2.725,0.635) 8(2.725,1.905)
  silkscreen extent -3.5,-2.5 0.9,2.5, body extent -3,-2.45 3,2.45, height 1.63
SRP1250 [mm] "BOURNS"
  rect 4x4.5 smd: 1(-5.5,0) 2(5.5,0)
  silkscreen extent -7,-6.8 7,6.8, body extent -6.95,-6.75 6.95,6.75, height 5.9
SSQ-106-02-G-D-RA [mm] "Samtec Right Angle Header"
  rrect6% 1.65x1.65 hole 1: 1(6.35,-1.283)
  round 1.65 hole 1: 2(6.35,1.257) 3(3.81,-1.283) 4(3.81,1.257) 5(1.27,-1.257) 6(1.27,1.283) 7(-1.27,-1.257) 8(-1.27,1.283) 9(-3.81,-1.257) 10(-3.81,1.283) 11(-6.35,-1.257) 12(-6.35,1.283)
  silkscreen extent -7.62,-11.43 8.43,2.53, body extent -7.62,-11.29 7.62,1.6, height 5.08
SW_7914G-1-000E [mm] "BOURNS"
  rect 1.27x1.27 smd: 1(-1.27,2.75) 2(-1.27,-2.75) 3(1.27,-2.75) 4(1.27,2.75)
  silkscreen extent -2.49,-2.06 2.44,2.14, body extent -2.5,-3.1 2.5,3.1, height 4.13
TI_Symbol_Overlay_Medium [mm]
  silkscreen extent -3.16,-3.09 3.16,3.06
TRANS_NexFET_Q5A [mm] "TI recommended land pattern (nominal) M0139-01"
  rect 0.75x0.675 smd paste-0.1 mask+0.051: 1(-2.776,1.917) 2(-2.776,0.639) 3(-2.776,-0.639) 4(-2.776,-1.917)
  rect 0.655x0.675 smd paste-0.1 mask+0.051: 5(2.776,-1.917) 6(2.776,-0.639) 7(2.776,0.639) 8(2.776,1.917)
  rect 4.295x4.51 smd paste-2.2 mask+0.051: 9(0.301,0)
  silkscreen extent -3.4,-2.8 3.4,2.8, body extent -3.05,-2.5 3.05,2.5, height 1.11
WE-LHMI_4020 [mm] "WERTH"
  rect 1.5x2.4 smd: 1(-1.85,0) 2(1.85,0)
  silkscreen extent -2.2,-2.2 2.2,2.2, body extent -2.15,-2.15 2.15,2.15, height 2

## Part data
C1 C10: "CAP, CERM, 1000 pF, 100 V, +/- 10%, X7R, 0603"
C2: "CAP, CERM, 0.047 µF, 50 V, +/- 10%, X7R, 0603"
C3 C4 C11 C14 C28 C29: "CAP, CERM, 10 µF, 50 V, +/- 10%, X7R, 1210"
C5 C12 C13 C20: "CAP, CERM, 22 µF, 35 V, +/- 20%, JB, 0805"
C6 C7 C8 C9: "CAP, CERM, 2.2 µF, 50 V, +/- 10%, X5R, 0805"
C15 C22 C30 C35 C36 C37 C38 C40 C42 C43 C44 C45 C47 C55 C58 C61 C62 C63: "CAP, CERM, 0.1 µF, 50 V, +/- 10%, X7R, 0603"
C16: "CAP, CERM, 220 pF, 50 V, +/- 1%, C0G/NP0, 0603"
C17: "CAP, CERM, 0.22 µF, 16 V, +/- 10%, X7R, 0603"
C18 C25: "CAP, CERM, 560 pF, 50 V, +/- 5%, C0G/NP0, 0603"
C19: "CAP, CERM, 8.2 pF, 50 V, +/- 3%, C0G/NP0, 0603"
C21: "CAP, CERM, 1 µF, 50 V, +/- 10%, X7R, 0603"
C23: "CAP, CERM, 1 µF, 10 V, +/- 10%, X6S, 0603"
C24: "CAP, CERM, 100 pF, 50 V, +/- 1%, C0G/NP0, 0603"
C26: "CAP, AL, 68 µF, 35 V, +/- 20%, 0.34 ohm, SMD"
C27: "CAP, Polymer Hybrid, 33 µF, 50 V, +/- 20%, 40 ohm, 6.3x7.7 SMD"
C31: "CAP, CERM, 0.82 µF, 25 V, +/- 10%, X7R, 0805"
C32 C33 C34 C39 C41 C56 C60: "CAP, CERM, 4.7 µF, 50 V, +/- 10%, X7R, 1206"
C46: "CAP, CERM, 0.22 µF, 16 V, +/- 5%, X7R, 0805"
C48 C49 C50 C51 C52 C53 C54 C64 C66 C68: "CAP, CERM, 0.01 µF, 100 V, +/- 5%, X7R, 0603"
C57 C65 C67: "CAP, CERM, 0.1 µF, 16 V, +/- 5%, X7R, 0603"
C59: "CAP, CERM, 22 µF, 10 V, +/- 20%, X5R, 0603"
D1: "Diode, Schottky, 40 V, 3 A, SMC"
D2: "Diode, Ultrafast, 100 V, 0.15 A, SOD-123"
D3 D4 D5 D12: "Diode, Schottky, 60 V, 1 A, SOD-323F"
D6 D8 D10 D13: "LED, Green, SMD"
D7 D9 D14: "Diode, Zener, 9.1 V, 200 mW, SOD-323"
D11: "Diode, Zener, 4.3 V, 200 mW, SOD-323"
D15: "LED, Red, SMD"
D16 D17 D18: "Diode, Schottky, 20 V, 0.2 A, SOD-523"
FID1 FID2 FID3 FID4 FID5 FID6: "Fiducial mark.  There is nothing to buy or mount."
GND_1 GND_2: "Test Point, Multipurpose, Black, TH"
H1 H3 H5 H7: "Standoff, Hex, 0.5\"L #4-40 Nylon"
H2 H4 H6 H8: "Machine Screw, Round, #4-40 x 1/4, Nylon, Philips panhead"
J1: "Terminal Block, 100mil, 2x1, 6A, 63V, TH"
J2: "Header, 100mil, 4x2, Tin, TH"
J3 J5: "Header, 100mil, 3x1, Tin, TH"
J4: "Header, 100mil, 2x1, Tin plated, TH"
J6 J7 J9: "Terminal Block, 5.08mm, 4x1, TH"
J8: "Receptacle, 100mil, 6x2, Gold, R/A, TH"
L1: "Ferrite Bead, 160 ohm @ 100 MHz, 6 A, 1206"
L2: "Inductor, Shielded Drum Core, Powdered Iron, 470 nH, 6.8 A, 0.0112 ohm, SMD"
L3: "Inductor, Powdered Iron, 10 µH, 10 A, 0.0255 ohm, SMD"
Logo1: library part TI_Logo, "Texas Instrument Corporate Signature"
Logo2: library part Pb-Free
Q1 Q2: "MOSFET, N-CH, 60 V, 5.4 A, SOIC-8"
Q3: "MOSFET, N-CH, 60 V, 19 A, SON 5x6mm"
Q4: "MOSFET, N-CH, 20 V, 6.7 A, DQK0006B"
R1: "RES, 2.00, 1%, 0.1 W, 0603"
R2 R25 R26 R40: "RES, 0, 5%, 0.1 W, 0603"
R3: "RES, 160 k, 1%, 0.1 W, 0603"
R4: "RES, 102 k, 1%, 0.1 W, 0603"
R5: "RES, 2.2 k, 5%, 0.1 W, 0603"
R6: "RES, 43, 5%, 0.1 W, 0603"
R7: "RES, 1.00 k, 1%, 0.1 W, 0603"
R8: "RES, 0.01, 1%, 4 W, 3015 WIDE"
R9: "RES, 10, 5%, 0.1 W, 0603"
R10: "RES, 51.1 k, 1%, 0.1 W, 0603"
R11 R12 R17 R31: "RES, 3.3 k, 5%, 0.1 W, 0603"
R13 R14: "RES, 680 k, 5%, 0.125 W, 0805"
R15 R16 R32: "RES, 59.0 k, 1%, 0.1 W, 0603"
R18 R19 R33: "RES, 42.2 k, 1%, 0.1 W, 0603"
R20 R21: "RES, 100 k, 1%, 0.1 W, 0603"
R22: "RES, 21.5 k, 1%, 0.125 W, 0805"
R23: "RES, 20 k, 5%, 0.125 W, 0805"
R24: "RES, 100 k, 1%, 0.125 W, 0805"
R27 R28 R41: "RES, 1.21 k, 1%, 0.1 W, 0603"
R29: "RES, 2.43 k, 1%, 0.1 W, 0603"
R30 R36 R37 R38: "RES, 10.0 k, 1%, 0.1 W, 0603"
R34: "RES, 470, 1%, 0.1 W, 0603"
R35: "RES, 57.6 k, 1%, 0.1 W, 0603"
R39: "RES, 2.55 k, 1%, 0.1 W, 0603"
R42: "RES, 47.0 k, 1%, 0.1 W, 0603"
S1: "Switch, Tactile, SPST-NO, 0.1A, 16V, SMT"
TP1 TP2 TP3 TP4 TP5: "Test Point, Miniature, Red, TH"
U1 U2 U3 U4: "Smart Diode Controller, DGK0008A"
U5: "4.5-V TO 52-V INPUT CURRENT MODE BOOST CONTROLLER, DGQ0010D"
U6: "LinCMOS Timer, D0008A"
U7 U8 U11: "Three-Channel Linear LED Driver with Analog and PWM Dimming, PWP0016F"
U9: "60-V, 5-µA IQ, 100-mA, Low-Dropout VOLTAGE REGULATOR With Enable and Power-Good, DGN0008C"
U10: "SINGLE BUFFER/DRIVER WITH OPEN-DRAIN OUTPUT, DBV0005A"
U12: "Automotive 75 nsec, 2.7V to 5V comparator with Rail-to-Rail Input and Output, DCK0005A"
ZZ1 ZZ2 ZZ3: library part AssemblyNote

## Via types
v1: diameter 0.508, hole 0.305, Top Layer to Bottom Layer, tented both sides, 203 vias
v2: diameter 0.77, hole 0.3, Top Layer to Bottom Layer, tented both sides, 96 vias
v3: diameter 0.4, hole 0.2, Top Layer to Bottom Layer, 18 vias
v4: diameter 0.5, hole 0.2, Top Layer to Bottom Layer, 9 vias

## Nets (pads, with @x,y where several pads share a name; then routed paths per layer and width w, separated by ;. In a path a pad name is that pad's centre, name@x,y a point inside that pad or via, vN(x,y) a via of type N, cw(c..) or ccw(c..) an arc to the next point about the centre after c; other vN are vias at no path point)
/FAULT: C38.1 C40.1 C57.1 J4.1 R21.1 TP4.1 U7.6 U8.6 U10.2 U11.6 | length 131
  Top Layer w0.381: U7.6@74.012,28.743 74.717,28.743 75.342,29.368 75.342,31.551 75.599,31.809 75.624,31.809 77.216,33.401 78.613,33.401 v2(78.613,35.56)
  Top Layer w0.432: U10.2@28.299,40.132 29.321,40.132 30.121,39.332 C57.1@30.988,39.332 32.514,39.332 v2(32.806,39.624) 32.806,40.984 v2(36.142,44.32) ; v2@66.507,5.629 U11.6@74.012,5.629 ; TP4.1@69.342,42.418 70.063,41.697 U8.6@74.012,41.697 ; C38.1@71.59,22.987 68.326,22.987 67.818,23.495 v2(67.818,24.257) 67.31,24.765 67.31,27.94 69.469,27.94 69.888,28.359 72.286,28.359 72.661,28.734 74.003,28.734 U7.6@74.012,28.743
  Bottom Layer w0.432: v2(32.806,39.624) 32.9,39.531 R21.1@34.197,39.531 ; v2(36.142,44.32) 38.062,46.24 63.395,46.24 64.516,45.119 C40.1@64.516,40.17 ; v2(66.294,5.842) 66.294,22.86 66.421,22.86 v2(67.818,24.257) ; J4.1@68.58,35.814 70.104,35.814 71.247,34.671 71.247,33.02 77.47,33.02 78.613,34.163 v2(78.613,35.56)
  Bottom Layer w0.762: C40.1@64.516,40.17 67.094,40.17 TP4.1@69.342,42.418 69.342,38.989 68.58,38.227 J4.1@68.58,35.814
/FAULT_S: C42.1 C43.1 C61.1 J4.2 R20.1 TP5.1 U7.7 U8.7 U11.7 | length 70.8
  Top Layer w0.432: R20.1@56.934,5.664 58.026,4.572 65.532,4.572 TP5.1@67.056,3.048 68.364,4.356 C61.1@71.374,4.356 72.174,4.356 72.797,4.979 U11.7@74.012,4.979 ; J4.2@68.58,33.274 69.088,33.274 70.358,34.544 70.358,39.878 71.527,41.047 U8.7@74.012,41.047 ; v2(70.104,25.146) 69.888,25.362 C42.1@69.888,26.924 72.136,26.924 72.896,27.684 72.896,28.076 72.904,28.084 U7.7@74.003,28.084
  Bottom Layer w0.432: TP5.1@67.056,3.048 67.056,4.829 67.345,5.118 67.345,6.823 68.869,8.347 68.869,9.833 67.414,11.288 67.414,22.456 v2(70.104,25.146) 70.104,28.486 C43.1@69.126,29.464
  Bottom Layer w0.762: J4.2@68.58,33.274 68.58,31.75 69.126,31.204 C43.1@69.126,29.464
BOOST_IN: C13.1 C14.1 C15.1 C20.2 C21.2 C22.2 C55.1 L2.2 L3.2 R2.1 R3.2 R30.2 R35.2 S1.1 S1.2 TP2.1 U5.10 U9.8 | length 95.7
  Top Layer w0.279: U5.10@51.755,29.448 U5.10@51.719,29.484 ; 52.239,29.817 52.238,29.816 52.238,29.484 U5.10@51.791,29.484 ; 52.42,29.943 52.25,29.943 U5.10@51.791,29.484 ; U5.10@51.699,29.484 51.185,29.997 51.141,29.997 51.24,29.898 51.24,29.493 51.249,29.484 U5.10@51.699,29.484 ; U5.10@51.699,29.484 U5.10@51.719,29.484 ; U5.10@51.719,29.484 U5.10@51.791,29.484
  Top Layer w0.432: R30.2@14.694,7.112 14.694,5.88 15.24,5.334 15.748,5.334 16.294,4.788 16.294,4.318 ; v2(17.526,4.191) 16.421,4.191 16.294,4.318 ; U9.8@19.111,3.089 16.507,3.089 C55.1@16.294,3.302 16.294,4.318 ; v2(33.909,10.795) 34.125,10.579 R35.2@35.687,10.579 35.687,14.737 36.571,15.621 TP2.1@38.354,15.621 ; L3.2@44.392,42.26 46.557,44.426 46.557,57.165 47.493,58.1 S1.2@48.838,58.1 S1.1@54.338,58.1 ; C22.2@49.652,33.212 49.652,31.456 R3.2@49.636,31.44 50.53,31.44 51.719,30.252 U5.10@51.719,29.514
  Bottom Layer w0.432: v2(17.526,4.191) 17.526,2.794 18.288,2.032 31.407,2.032 32.131,2.756 32.131,9.017 v2(33.909,10.795) ; TP2.1@38.354,15.621 40.259,17.526 v2(40.259,22.479)
  Bottom Layer w1.016: 40.522,35.768 40.692,35.938 C20.2@52.492,35.938
  other v2: 41.275,22.479 42.291,22.479 43.307,22.479 40.259,23.368 41.275,23.368 42.291,23.368 43.307,23.368 52.078,31.317 40.716,40.759 41.605,40.759 40.716,41.775 41.605,41.775 40.716,42.791 41.605,42.791 40.716,43.807 41.605,43.807
BOOST_OUT: C26.1 C27.1 C28.1 C29.1 C30.1 C39.2 C41.2 C44.2 C45.2 C60.2 C62.2 D1.1 R10.2 TP3.1 U7.1 U8.1 U8.3 U8.4 U8.5 U11.1 U11.3 U11.4 U11.5 | length 195.7
  Top Layer w0.432: R10.2@38.263,30.965 36.747,32.481 36.747,35.357 36.747,43.792 36.943,43.989 36.943,44.652 36.747,44.849 36.747,46.958 39.997,50.209 v2(43.208,50.209) ; TP3.1@49.276,14.732 51.435,16.891 v2(54.229,16.891) ; v2(58.547,8.382) 58.547,7.088 59.613,6.022 C60.2@62.23,6.022 62.23,7.849 62.763,8.382 64.516,8.382 66.694,10.56 70.72,10.56 v2(72.136,9.144) 72.401,8.879 U11.1@74.012,8.879 74.012,10.258 74.422,10.668 C62.2@76.67,10.668 76.67,11.176 77.686,12.192 79.756,12.192 80.772,11.176 81.316,11.176 81.824,10.668 83.439,10.668 84.709,11.938 84.709,21.59 94.107,21.59 94.615,22.098 94.615,25.646 94.226,26.035 89.154,26.035 88.9,26.289 88.9,32.385 88.66,32.625 80.913,32.625 79.664,33.874 79.664,35.995 79.048,36.611 78.178,36.611 77.562,35.995 77.562,34.872 C39.2@76.2,34.872 ; 71.262,49.441 71.442,49.441 72.136,48.746 72.136,45.466 72.655,44.947 U8.1@74.012,44.947 ; v2(72.136,6.858) 72.207,6.929 U11.4@74.012,6.929 ; v2@72.136,42.926 72.207,42.997 U8.4@74.012,42.997 ; C44.2@72.865,35.268 72.865,32.545 73.417,31.993 U7.1@74.012,31.993 ; v2(73.914,38.989) 74.348,38.555 74.348,34.872 ; U11.5@74.012,6.279 U11.4@74.012,6.929 ; U11.3@74.012,7.579 U11.4@74.012,6.929 ; U8.5@74.012,42.347 U8.4@74.012,42.997 ; U8.3@74.012,43.647 U8.4@74.012,42.997
  Top Layer w0.762: C28.1@72.719,52.578 ccw(c72.719,52.831) C28.1@72.898,52.652 ; C44.2@72.865,35.268 73.952,35.268 74.348,34.872 C39.2@76.2,34.872
  Bottom Layer w0.432: v2(43.208,50.209) 43.324,50.324 v2(69.408,50.324) ; v2(54.229,16.891) 54.864,16.256 54.864,13.97 55.372,13.462 57.277,13.462 58.547,12.192 v2(58.547,8.382) ; C29.1@72.104,47.239 72.168,47.175 v2(72.168,42.914) ; v2(72.136,6.858) v2(72.136,9.144) ; v2@72.136,42.926 73.914,41.148 v2(73.914,38.989)
  Bottom Layer w0.762: C41.2@72.898,50.302 74.666,50.302 74.968,50 C45.2@76.358,50
  other v2: 69.45,49.368 70.49,49.368 70.469,50.324
EN1: C33.2 C37.2 D9.1 D16.2 R16.2 R19.2 U8.2 | length 104.2
  Top Layer w0.432: D16.2@42.418,9.694 43.349,9.694 43.688,10.033 v2(43.688,11.176) ; v2(68.126,46.838) 68.228,46.736 69.342,46.736 69.342,45.212 70.257,44.297 U8.2@74.012,44.297
  Bottom Layer w0.381: C33.2@30.734,44.122 33.557,44.122 ; v2(43.688,11.176) 38.674,11.176 35.126,14.724 35.126,31.388 37.3,33.562 37.3,34.052 37.678,34.429 37.678,34.431 37.698,34.451 37.698,40.727 34.303,44.122 33.557,44.122 ; v2(68.126,46.838) 67.987,46.977 C37.2@33.531,46.977 33.531,44.147 33.557,44.122
  Bottom Layer w0.432: R16.2@20.104,43.688 R19.2@23.152,43.688 ; R19.2@23.114,43.726 26.624,43.726 D9.1@26.67,43.772 28.95,43.772 29.3,44.122 C33.2@30.734,44.122
EN2: C56.2 C58.2 D14.1 D17.2 R32.2 R33.2 U11.2 | length 70.8
  Top Layer w0.432: v2(25.527,12.192) 28.194,12.192 v2(33.147,7.239) ; D17.2@45.212,9.694 45.212,10.922 v2(45.466,11.176) ; v2(64.389,6.858) 65.278,6.858 v2(67.818,9.398) 68.288,8.928 C58.2@69.85,8.928 70.549,8.229 71.565,8.229 71.701,8.093 72.571,8.093 72.707,8.229 U11.2@74.012,8.229
  Bottom Layer w0.432: R32.2@15.278,15.24 16.764,15.24 17.018,14.986 17.018,13.038 18.204,13.038 18.504,12.738 R33.2@19.812,12.738 21.076,12.738 21.472,13.134 C56.2@23.368,13.134 24.585,13.134 v2(25.527,12.192) ; v2(33.147,7.239) 33.274,7.366 45.466,7.366 ; v2(45.466,11.176) 45.466,7.366 ; v2(64.389,6.858) 63.881,7.366 45.466,7.366
EN3: C32.2 C36.2 D7.1 D18.2 R15.2 R18.2 U7.2 | length 88.4
  Top Layer w0.432: v2(47.49,11.123) 48.006,10.606 D18.2@48.006,9.694 49.826,9.694 51.562,11.43 51.562,13.716 53.086,15.24 66.548,15.24 66.548,30.48 66.802,30.734 70.612,30.734 71.221,31.343 U7.2@74.012,31.343
  Bottom Layer w0.432: R15.2@19.85,22.098 22.352,22.098 D7.1@22.352,20.15 23.538,20.15 23.838,19.85 R18.2@25.146,19.85 26.378,19.85 26.924,20.396 C32.2@28.806,20.396 ; C32.2@28.702,20.292 C32.2@28.806,20.396 ; v2(47.49,11.123) 47.49,11.889 47.148,12.231 45.066,12.231 44.534,11.698 44.534,10.222 43.953,9.641 36.861,9.641 36.449,10.052 36.449,11.188 34.145,13.492 34.145,14.098 33.989,14.253 33.989,19.024 33.163,19.85 C36.2@31.75,19.85 30.723,19.85 30.073,20.5 C32.2@28.702,20.5 C32.2@28.806,20.396
LDO_OUT: C35.2 C59.1 C65.2 J3.1 J5.1 R13.2 R20.2 R21.2 R34.2 R37.2 U6.8 U9.1 U10.5 U12.5 | length 186.8
  Top Layer w0.432: v2@11.557,10.077 12.798,10.077 12.808,10.068 21.809,10.068 22.644,9.233 C59.1@22.644,7.112 24.13,7.112 24.892,6.35 ; R34.2@22.479,48.589 22.479,47.627 23.368,46.739 v2(23.368,39.624) 23.81,39.182 U10.5@25.549,39.182 ; U9.1@23.561,3.089 24.679,3.089 ; R37.2@26.378,7.112 25.616,6.35 24.892,6.35 ; U12.5@36.975,2.906 36.333,2.264 ; R20.2@55.334,5.664 53.353,5.664 53.302,5.715 ; J3.1@68.58,13.462 68.557,13.439 66.213,13.439 65.298,14.354 61.09,14.354 59.436,12.7 59.436,10.922 57.112,8.598 57.112,6.947 53.302,6.947 53.302,5.715 ; 24.679,3.089 27.556,3.089 28.381,2.264 36.333,2.264 ; 24.679,3.089 24.892,3.302 24.892,6.35 ; 36.333,2.264 37.624,2.264 37.768,2.12 38.432,2.12 38.576,2.264 52.264,2.264 52.264,2.391 53.302,3.429 53.302,5.715
  Top Layer w0.508: U6.8@77.597,14.547 78.809,14.547 v2(78.994,14.732) 80.264,13.462 J5.1@82.042,13.462
  Bottom Layer w0.432: v2(11.557,10.16) 11.557,11.811 9.779,13.589 8.128,13.589 7.366,14.351 7.366,16.002 10.83,19.466 10.83,27.455 9.493,28.792 9.493,37.273 10.479,38.259 12.78,38.259 16.79,42.269 20.309,42.269 22.954,39.624 v2(23.368,39.624) 23.368,39.574 25.011,37.931 R21.2@34.197,37.931 ; R13.2@72.009,24.13 70.612,22.733 70.612,15.494 J3.1@68.58,13.462 69.469,13.462 72.644,10.287 78.867,10.287 J5.1@82.042,13.462
  Bottom Layer w0.508: C35.2@78.486,16.726 78.486,15.24 v2(78.994,14.732)
NetC1_1: C1.1 R1.1 | length 2.3
  Bottom Layer w1.016: R1.1@5.499,34.163 7.658,34.163 C1.1@7.747,34.252
NetC2_1: C2.1 C3.1 C4.1 C5.1 J2.1 J2.3 J2.5 J2.7 L1.2 R1.2 | length 23.5
  Top Layer w1.016: J2.1@2.54,47.625 J2.3@2.54,45.085 J2.5@2.54,42.545 J2.7@2.54,40.005 2.54,35.598 C2.1@2.502,35.56 2.487,35.545 C3.1@2.487,31.496 2.794,31.189 L1.2@2.794,27.231
  Bottom Layer w1.016: R1.2@3.899,34.163 3.899,31.28 C5.1@3.937,31.242
  other v2: 4.572,27.178 4.572,28.067 3.937,28.829 4.826,28.956
NetC6_1: C6.1 U1.7 | length 5.3
  Top Layer w0.432: C6.1@15.494,41.402 15.494,39.116 16.693,37.917 U1.7@17.973,37.917
NetC6_2: C6.2 U1.1 | length 2.9
  Top Layer w0.432: C6.2@13.462,41.402 13.462,38.628 U1.1@13.523,38.567
NetC7_1: C7.1 U2.7 | length 5.2
  Top Layer w0.432: C7.1@15.494,32.766 15.494,30.506 16.719,29.281 U2.7@17.973,29.281
NetC7_2: C7.2 U2.1 | length 2.9
  Top Layer w0.432: C7.2@13.462,32.766 13.462,29.992 U2.1@13.523,29.931
NetC8_1: C8.1 U3.7 | length 5.3
  Top Layer w0.432: C8.1@15.494,24.13 15.494,21.844 16.693,20.645 U3.7@17.973,20.645
NetC8_2: C8.2 U3.1 | length 2.9
  Top Layer w0.432: C8.2@13.462,24.13 13.462,21.356 U3.1@13.523,21.295
NetC9_1: C9.1 U4.7 | length 5.3
  Top Layer w0.432: C9.1@15.494,15.494 15.494,13.18 16.665,12.009 U4.7@17.973,12.009
NetC9_2: C9.2 U4.1 | length 3.1
  Top Layer w0.508: C9.2@13.208,15.494 C9.2@13.462,15.494 13.523,15.433 U4.1@13.523,12.688
NetC10_1: C10.1 C11.1 C12.1 L2.1 Q1.5 Q1.6 Q1.7 Q1.8 Q2.5 Q2.6 Q2.7 Q2.8 R2.2 TP1.1 U1.8 U2.8 U3.8 U4.8 | length 49.2
  Top Layer w0.432: U4.8@17.973,12.659 23.581,12.659 25.019,14.097 Q2.5@27.109,14.097 ; U3.8@17.973,21.295 19.771,21.295 ; U2.8@17.973,29.931 19.812,29.931 ; U1.8@17.973,38.567 22.524,38.567 25.912,35.179 Q1.8@27.109,35.179 ; Q2.8@27.109,17.907 25.527,17.907 22.139,21.295 19.771,21.295 ; Q1.5@27.109,31.369 25.019,31.369 23.581,29.931 19.812,29.931 ; 19.771,21.295 19.812,21.336 19.812,29.931
NetC16_1: C16.1 R3.1 U5.1 | length 4.8
  Top Layer w0.279: v2(46.355,29.845) 46.752,29.448 U5.1@47.305,29.448 48.036,30.179 R3.1@48.036,31.44
  Bottom Layer w0.432: C16.1@46.228,31.204 46.355,31.077 v2(46.355,29.845)
NetC17_1: C17.1 U5.2 | length 4
  Top Layer w0.254: C17.1@46.145,31.415 46.145,30.557 46.06,30.557 45.643,30.14 45.643,29.55 46.06,29.133 46.407,29.133 46.559,28.981 46.572,28.981 46.582,28.971 47.282,28.971 U5.2@47.305,28.948
NetC18_1: C18.1 C19.1 U5.4 | length 8.4
  Top Layer w0.254: C19.1@43.324,28.121 43.497,27.948 U5.4@47.305,27.948
  Top Layer w0.432: C18.1@43.212,32.457 43.212,28.233 C19.1@43.324,28.121
NetC18_2: C18.2 R4.2 | length 3.9
  Top Layer w0.432: R4.2@40.754,29.393 40.754,32.416 40.795,32.457 C18.2@41.612,32.457
NetC19_2: C19.2 R4.1 R5.2 R10.1 U5.5 | length 12.9
  Top Layer w0.279: 45.403,27.448 U5.5@47.305,27.448
  Top Layer w0.305: C19.2@43.324,26.521 44.476,26.521 45.403,27.448
  Top Layer w0.432: R10.1@38.263,29.365 39.203,29.365 39.449,29.119 39.449,29.098 R4.1@40.754,27.793 41.83,27.793 42.271,27.352 42.271,26.681 42.431,26.521 C19.2@43.324,26.521 ; U5.5@47.305,27.382 47.519,27.168 R5.2@47.519,25.536
NetC23_1: C23.1 U5.9 | length 4.8
  Top Layer w0.279: U5.9@51.755,28.948 54.096,28.948 54.559,29.412 C23.1@54.559,31.17
NetC24_1: C24.1 R7.1 U5.7 | length 5.5
  Top Layer w0.254: U5.7@51.755,27.948 52.824,27.948 53.556,27.216 C24.1@54.356,27.216 54.521,27.051 R7.1@56.858,27.051 ; R7.1@56.82,27.216 R7.1@56.858,27.178
NetC25_1: C25.1 D1.2 L3.1 Q3.5 Q3.6 Q3.7 Q3.8 Q3.9
  other v2: 62.683,31.325 62.667,32.234
NetC25_2: C25.2 R9.2 | length 4.3
  Bottom Layer w0.635: C25.2@61.055,30.031 61.055,28.964 61.662,28.358 62.523,28.358 62.922,27.959 R9.2@62.922,26.972
NetC31_1: C31.1 D2.1 R14.1 U6.2 U6.6 | length 26.6
  Top Layer w0.508: D2.1@60.96,12.051 63.894,12.051 R14.1@64.008,11.938 ; v2(63.985,13.1) 64.008,13.078 R14.1@64.008,11.938 ; U6.2@76.327,19.997 76.327,18.415 75.057,17.145 U6.6@75.057,14.547 75.057,12.827 74.93,12.7 70.866,12.7 70.104,11.938 R14.1@64.008,11.938
  Bottom Layer w0.508: C31.1@63.952,16.347 63.952,13.134 v2(63.985,13.1)
NetC34_1: C34.1 D5.1 R17.2 R22.2 | length 38.6
  Top Layer w0.432: v2(17.78,39.878) 17.78,56.259 18.539,57.018 22.432,57.018 R17.2@22.479,56.971
  Bottom Layer w0.432: D5.1@15.578,33.02 19.738,33.02 C34.1@19.812,32.946 ; v2(17.78,39.878) 19.812,37.846 C34.1@19.812,32.946 ; R22.2@24.892,32.766 24.712,32.946 C34.1@19.812,32.946
NetC46_1: C46.1 U6.5 | length 4.3
  Top Layer w0.508: v2(72.136,13.97) 72.713,14.547 U6.5@73.787,14.547
  Bottom Layer w0.508: v2(72.136,13.97) 72.39,14.224 C46.1@72.39,16.256
NetC47_1: C47.1 D11.1 Q4.2 R22.1 R23.2 | length 63
  Top Layer w0.305: Q4.2@50.886,3.81 51.181,3.81 51.689,4.318 v2(51.689,8.255)
  Top Layer w0.33: v2(37.339,11.12) 42.113,11.12 43.192,12.199 v2(48.638,12.199) ; v2(51.689,8.255) v2@51.816,8.128
  Bottom Layer w0.305: v2(48.638,12.199) 49.315,12.199 49.782,11.732 49.782,9.459 50.986,8.255 v2(51.689,8.255)
  Bottom Layer w0.33: R23.2@32.186,35.679 32.402,35.463 C47.1@34.726,35.463 35.352,34.836 35.352,34.728 35.566,34.514 35.566,33.261 35.591,33.236 34.726,32.371 34.726,32.265 34.57,32.109 34.57,14.494 34.726,14.338 34.726,13.733 v2(37.339,11.12)
  Bottom Layer w0.432: R22.1@24.892,30.734 26.85,30.734 27.332,31.217 27.332,35.296 27.712,35.675 D11.1@29.055,35.675 31.462,35.675 R23.2@31.632,35.845
NetC48_1: C48.1 J5.3 R24.2 U6.3 | length 13.7
  Top Layer w0.508: U6.3@75.057,19.997 75.057,22.479 75.438,22.86 R24.2@76.962,22.86 78.74,22.86 78.994,23.114 C48.1@80.988,23.114 80.988,21.12 82.042,20.066 J5.3@82.042,18.542
NetC63_1: C63.1 R35.1 R36.2 R39.1 | length 10.2
  Top Layer w0.432: R35.1@35.687,8.979 35.725,9.017 C63.1@38.824,9.017 38.824,8.263 39.086,8.001 40.259,8.001 40.856,7.404 R36.2@40.856,6.604 R39.1@37.757,6.604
